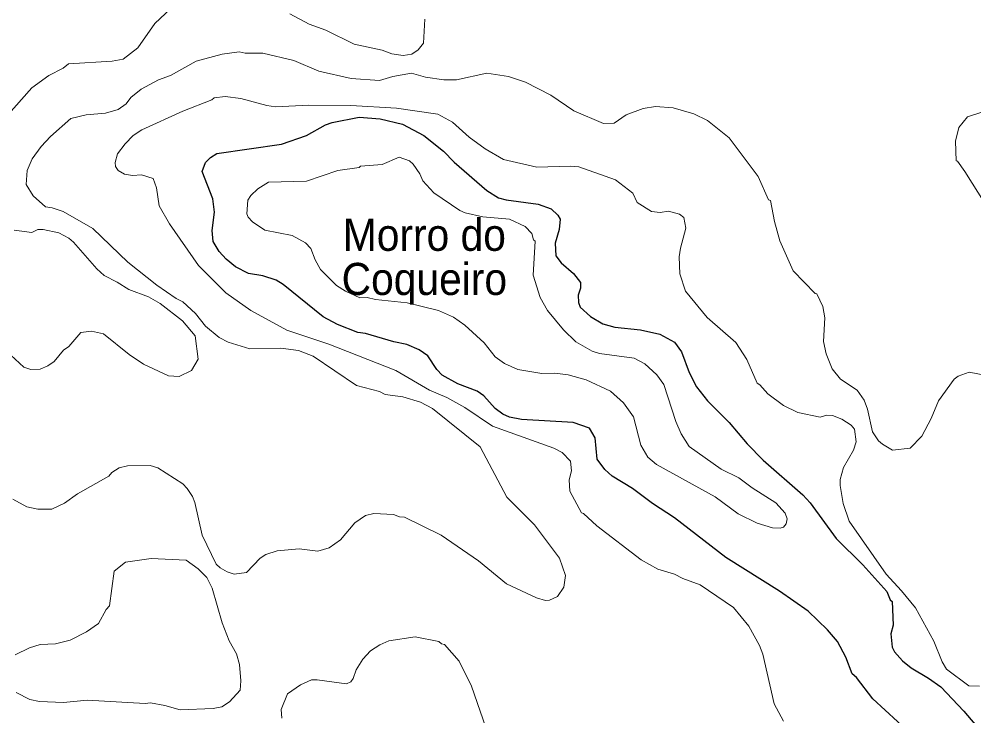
# Model space of a CAD drawing. Extents: x 447.8 to 473.9, y 7733.1 to 7760.8.
# Drawn here: x 456.578 to 458.959, y 7735.076 to 7736.813 of the extents above; entities that cross this region are included whole.
import ezdxf
from ezdxf.enums import TextEntityAlignment as Align

# ---------------------------------------------------------------- set-up
doc = ezdxf.new("R2010")
doc.units = 0
doc.header["$LTSCALE"] = 0.032
doc.layers.add('1', color=7, linetype='Continuous', lineweight=25)
doc.layers.add('2', color=7, linetype='Continuous', lineweight=13)
doc.layers.add('27', color=7, linetype='Continuous')

msp = doc.modelspace()

# ---------------------------------------------------------------- linework, layer by layer
at = {"layer": '1'}
for points in [[(458.7986, 7735.0336), (458.7063, 7735.1184), (458.6661, 7735.1714), (458.6556, 7735.1805), (458.6391, 7735.2227), (458.6189, 7735.2611), (458.5933, 7735.2907), (458.5457, 7735.3367), (458.4742, 7735.3871), (458.3405, 7735.4709), (458.2125, 7735.5693), (458.1571, 7735.6057), (458.1078, 7735.6428), (458.0567, 7735.6734), (458.0385, 7735.69), (458.0196, 7735.7159), (458.0148, 7735.7687), (458.0003, 7735.7929), (457.9595, 7735.8074), (457.8304, 7735.8148), (457.8005, 7735.8208), (457.7839, 7735.828), (457.7653, 7735.8422), (457.7369, 7735.8738), (457.7206, 7735.8852), (457.6722, 7735.9038), (457.6334, 7735.9256), (457.62, 7735.9396), (457.5972, 7735.9731), (457.576, 7735.988), (457.5446, 7736.0021), (457.5126, 7736.0086), (457.4416, 7736.0295), (457.4226, 7736.0315), (457.3718, 7736.0516), (457.3361, 7736.0703), (457.2367, 7736.1511), (457.2195, 7736.1622), (457.1855, 7736.173), (457.1502, 7736.1784), (457.1179, 7736.1955), (457.0943, 7736.2141), (457.0771, 7736.2337), (457.0618, 7736.258), (457.0594, 7736.2856), (457.065, 7736.3314), (457.0613, 7736.3647), (457.0346, 7736.4328), (457.0431, 7736.4556), (457.0551, 7736.4677), (457.0714, 7736.4776), (457.2324, 7736.5011), (457.295, 7736.523), (457.3423, 7736.5489), (457.3591, 7736.5547), (457.4257, 7736.5681), (457.4785, 7736.5641), (457.5338, 7736.5505), (457.5876, 7736.5222), (457.6359, 7736.4838), (457.6631, 7736.4565), (457.7441, 7736.3852), (457.7734, 7736.367), (457.7924, 7736.3622), (457.8726, 7736.3518), (457.9051, 7736.3395), (457.9215, 7736.324), (457.9274, 7736.3138), (457.925, 7736.2885), (457.9146, 7736.2544), (457.9162, 7736.2231), (457.9296, 7736.2053), (457.9603, 7736.1786), (457.9775, 7736.156), (457.9778, 7736.1419), (457.9724, 7736.1249), (457.9733, 7736.1066), (457.9772, 7736.0945), (458.0026, 7736.0716), (458.0338, 7736.0535), (458.0634, 7736.0448), (458.1278, 7736.0383), (458.1756, 7736.0272), (458.2125, 7736.0071), (458.2296, 7735.9838)], [(458.2296, 7735.9838), (458.249, 7735.9323), (458.2672, 7735.8959), (458.2941, 7735.8612), (458.3488, 7735.807), (458.3934, 7735.7543)], [(458.3934, 7735.7543), (458.4337, 7735.7132), (458.5321, 7735.6269), (458.5505, 7735.6068), (458.6157, 7735.5184), (458.6816, 7735.4525), (458.7416, 7735.3861), (458.7498, 7735.3653), (458.7545, 7735.3609), (458.757, 7735.3025), (458.7515, 7735.2808), (458.7547, 7735.2472), (458.7609, 7735.2354), (458.7806, 7735.2133), (458.802, 7735.1962), (458.8453, 7735.1705), (458.8762, 7735.1481), (458.934, 7735.0879), (459.0258, 7734.9793)]]:
    msp.add_lwpolyline(points, dxfattribs=at)
at = {"layer": '2'}
for points in [[(456.9701, 7736.8517), (456.9163, 7736.8019), (456.8745, 7736.741), (456.8377, 7736.7132), (456.8105, 7736.708), (456.7013, 7736.7016), (456.6878, 7736.6907), (456.6522, 7736.6724), (456.6102, 7736.6417), (456.5258, 7736.5476)], [(457.5897, 7736.8129), (457.5865, 7736.7524), (457.573, 7736.7364), (457.5576, 7736.725), (457.5356, 7736.7222), (457.5074, 7736.7262), (457.483, 7736.735), (457.4138, 7736.7504), (457.3432, 7736.785), (457.3016, 7736.8001), (457.2535, 7736.8258)], [(456.8449, 7736.6016), (456.8566, 7736.6171), (456.8824, 7736.6381), (456.9261, 7736.6614), (456.9556, 7736.6723), (457.0195, 7736.7077), (457.0841, 7736.7253), (457.1271, 7736.7309), (457.1415, 7736.7278), (457.1859, 7736.7276), (457.2629, 7736.7092), (457.3259, 7736.6833), (457.4058, 7736.6649), (457.4769, 7736.6596), (457.5098, 7736.6694), (457.5563, 7736.6779), (457.5913, 7736.6679), (457.6372, 7736.6611), (457.669, 7736.6613), (457.7447, 7736.6779), (457.7983, 7736.6699), (457.8405, 7736.6557), (457.904, 7736.623), (457.9615, 7736.5841), (458.0349, 7736.5522), (458.0614, 7736.5537), (458.0919, 7736.5742), (458.1345, 7736.5895), (458.1647, 7736.5946), (458.2087, 7736.5913), (458.2603, 7736.5769), (458.2946, 7736.5598), (458.3488, 7736.5164), (458.4208, 7736.4206), (458.4468, 7736.3626), (458.4515, 7736.3603), (458.4612, 7736.308), (458.4748, 7736.26), (458.5078, 7736.1853), (458.5631, 7736.1288), (458.5669, 7736.128), (458.5821, 7736.0968), (458.5871, 7736.0685), (458.584, 7736.0095), (458.5902, 7735.9785), (458.6054, 7735.9407), (458.6258, 7735.9149), (458.6679, 7735.8876), (458.6855, 7735.863), (458.6938, 7735.8408), (458.7055, 7735.7842), (458.7209, 7735.7613), (458.7304, 7735.7529), (458.7558, 7735.7386), (458.7998, 7735.7437), (458.829, 7735.7736), (458.8524, 7735.8172), (458.8704, 7735.8611), (458.9094, 7735.915), (458.9194, 7735.9227), (458.947, 7735.9325), (458.9857, 7735.9255)], [(456.6567, 7736.5199), (456.7075, 7736.5646), (456.7452, 7736.5745), (456.794, 7736.5786), (456.8253, 7736.5872), (456.8449, 7736.6016)], [(457.9499, 7735.6648), (457.9553, 7735.6869), (457.953, 7735.7109), (457.9319, 7735.7323), (457.9114, 7735.7433), (457.7583, 7735.7983), (457.6894, 7735.8448), (457.6449, 7735.8694), (457.6016, 7735.8878), (457.5173, 7735.9372), (457.3507, 7736.0029), (457.2457, 7736.0377), (457.1563, 7736.0863), (457.0937, 7736.1307), (457.0254, 7736.1989), (456.9529, 7736.3025), (456.9272, 7736.3474), (456.9207, 7736.3923), (456.9125, 7736.4158), (456.8837, 7736.4247), (456.861, 7736.4232), (456.8408, 7736.4263), (456.8255, 7736.4351), (456.8184, 7736.4457), (456.8181, 7736.4555), (456.8234, 7736.4768), (456.8423, 7736.5019), (456.8627, 7736.5223), (456.8845, 7736.5365), (456.9864, 7736.5836), (457.059, 7736.6114), (457.0642, 7736.6161), (457.0918, 7736.6195), (457.1311, 7736.6152), (457.196, 7736.5971), (457.2176, 7736.5938), (457.3003, 7736.5978), (457.4056, 7736.5971), (457.519, 7736.5906), (457.6225, 7736.5754), (457.6589, 7736.5561), (457.7, 7736.5183), (457.7398, 7736.4896), (457.786, 7736.4625), (457.8694, 7736.444), (457.9522, 7736.4464), (457.9739, 7736.4447), (458.0653, 7736.4121), (458.1082, 7736.3785), (458.1189, 7736.356), (458.1547, 7736.3335), (458.1763, 7736.331), (458.1971, 7736.334), (458.2243, 7736.3267), (458.2354, 7736.3182), (458.2407, 7736.2916), (458.2268, 7736.2419), (458.2241, 7736.2204), (458.2257, 7736.1778), (458.2394, 7736.1347), (458.2935, 7736.0691), (458.365, 7736.0063), (458.3923, 7735.9646), (458.418, 7735.9057), (458.425, 7735.9013), (458.4446, 7735.8784), (458.484, 7735.8498), (458.5196, 7735.8326), (458.5756, 7735.8204), (458.5923, 7735.8259), (458.6059, 7735.825), (458.6295, 7735.816), (458.6528, 7735.801), (458.6614, 7735.7909), (458.6655, 7735.7591), (458.6583, 7735.7382), (458.6337, 7735.6952), (458.6249, 7735.6656), (458.6249, 7735.6501), (458.6329, 7735.6052), (458.6477, 7735.5614), (458.74, 7735.4294), (458.7785, 7735.3877), (458.8128, 7735.345), (458.859, 7735.2621), (458.8799, 7735.2108), (458.8904, 7735.1924), (458.9464, 7735.1507), (458.9727, 7735.1502)], [(458.9865, 7736.3522), (458.9364, 7736.433), (458.9174, 7736.4587), (458.9141, 7736.4597), (458.9126, 7736.5084), (458.9214, 7736.5425), (458.9428, 7736.5693), (458.976, 7736.5802)], [(456.5624, 7735.616), (456.5974, 7735.5974), (456.625, 7735.5912), (456.6596, 7735.5912), (456.6914, 7735.6063), (456.7241, 7735.6299), (456.8019, 7735.6736), (456.8095, 7735.6825), (456.8279, 7735.6945), (456.8482, 7735.6993), (456.9046, 7735.7), (456.9237, 7735.6941), (456.9863, 7735.6544), (456.9975, 7735.6431), (457.0106, 7735.6228), (457.0167, 7735.6075), (457.0346, 7735.5266), (457.0694, 7735.4546), (457.0797, 7735.445), (457.0972, 7735.435), (457.1142, 7735.4292), (457.1455, 7735.4331), (457.1794, 7735.4689), (457.1932, 7735.478), (457.2213, 7735.4874), (457.2766, 7735.4925), (457.3234, 7735.4869), (457.3516, 7735.4947), (457.3793, 7735.5145), (457.4152, 7735.5574), (457.4418, 7735.5757), (457.4626, 7735.5806), (457.5119, 7735.5779), (457.527, 7735.5719), (457.5389, 7735.5713), (457.6308, 7735.5261), (457.7233, 7735.4626), (457.7937, 7735.4056), (457.8681, 7735.3702), (457.8909, 7735.3639), (457.9005, 7735.3643), (457.9209, 7735.374), (457.9362, 7735.3972), (457.9402, 7735.4259), (457.9258, 7735.4692), (457.8631, 7735.5521), (457.7946, 7735.6214), (457.7274, 7735.7467), (457.6087, 7735.8424), (457.5792, 7735.8582), (457.5346, 7735.8716), (457.491, 7735.8774), (457.4766, 7735.8845), (457.4196, 7735.8995), (457.3115, 7735.9727), (457.2746, 7735.9871), (457.2304, 7735.9926), (457.1531, 7735.9911), (457.0995, 7736.0071), (457.0774, 7736.0194), (457.043, 7736.0474), (457.0182, 7736.0786), (456.9866, 7736.1078), (456.9701, 7736.1163), (456.9219, 7736.1499), (456.8496, 7736.2068), (456.7622, 7736.2906), (456.6884, 7736.3332), (456.6606, 7736.3426), (456.6442, 7736.3449), (456.6136, 7736.372), (456.5961, 7736.4001), (456.5984, 7736.4356), (456.6109, 7736.4641), (456.6334, 7736.495), (456.6567, 7736.5199)], [(456.5663, 7736.2867), (456.6101, 7736.2805), (456.6248, 7736.2886), (456.6378, 7736.2885), (456.6775, 7736.2801), (456.7023, 7736.2666), (456.714, 7736.2569), (456.7718, 7736.1899), (456.7899, 7736.1733), (456.8226, 7736.1571), (456.852, 7736.1384), (456.9008, 7736.1204), (456.9297, 7736.1042), (456.9855, 7736.0608), (457.0168, 7736.0233), (457.0248, 7735.965), (457.0079, 7735.9366), (456.9772, 7735.9223), (456.9504, 7735.924), (456.8881, 7735.9527), (456.8526, 7735.9767), (456.789, 7736.0279), (456.7584, 7736.035), (456.7321, 7736.0317), (456.7023, 7735.9964), (456.6886, 7735.9874), (456.6655, 7735.9597), (456.6495, 7735.9484), (456.6304, 7735.9406), (456.6076, 7735.939), (456.5899, 7735.9453), (456.5577, 7735.9754)], [(458.1291, 7735.4654), (458.0183, 7735.55), (457.9856, 7735.5809), (457.9802, 7735.5818), (457.9512, 7735.6362), (457.9499, 7735.6648)], [(456.5706, 7735.134), (456.605, 7735.117), (456.6292, 7735.1117), (456.6888, 7735.1094), (456.7481, 7735.115), (456.8927, 7735.107), (456.9062, 7735.1085), (456.9415, 7735.1021), (456.9796, 7735.0909), (457.0624, 7735.0941), (457.0835, 7735.0987), (457.1028, 7735.1111), (457.1291, 7735.1404), (457.1307, 7735.1631), (457.1276, 7735.2045), (457.1203, 7735.2305), (457.1021, 7735.2635), (457.0846, 7735.3077), (457.0593, 7735.3948), (457.0464, 7735.4211), (457.0246, 7735.4428), (456.9944, 7735.4645), (456.9075, 7735.4684), (456.8438, 7735.4588), (456.815, 7735.437), (456.8036, 7735.3507), (456.7956, 7735.3415), (456.7758, 7735.3061), (456.7466, 7735.2852), (456.7059, 7735.2649), (456.6686, 7735.256), (456.6305, 7735.2544), (456.6045, 7735.2454), (456.5682, 7735.2281)], [(458.4839, 7735.0633), (458.461, 7735.1062), (458.4325, 7735.23), (458.4243, 7735.2515), (458.3977, 7735.2996), (458.3593, 7735.3458), (458.2761, 7735.4031), (458.2333, 7735.4181), (458.212, 7735.4294), (458.1708, 7735.4421), (458.1291, 7735.4654)], [(457.2332, 7735.0704), (457.2319, 7735.0917), (457.2477, 7735.1308), (457.2798, 7735.1534), (457.3073, 7735.166), (457.3215, 7735.1662), (457.3946, 7735.156), (457.405, 7735.1611), (457.4112, 7735.1695), (457.4186, 7735.1905), (457.4353, 7735.2178), (457.4545, 7735.2383), (457.4773, 7735.253), (457.4997, 7735.2633), (457.5659, 7735.2735), (457.6249, 7735.2617), (457.6312, 7735.256), (457.6391, 7735.2541), (457.6751, 7735.2124), (457.7063, 7735.1499), (457.771, 7734.963)]]:
    msp.add_lwpolyline(points, dxfattribs=at)
msp.add_lwpolyline([(457.9923, 7735.914), (458.0527, 7735.8858), (458.0848, 7735.8562), (458.1101, 7735.8217), (458.1284, 7735.7504), (458.1461, 7735.7212), (458.1677, 7735.7026), (458.3136, 7735.6217), (458.371, 7735.5797), (458.4187, 7735.5564), (458.4568, 7735.5445), (458.476, 7735.5438), (458.4842, 7735.5461), (458.4909, 7735.5544), (458.4933, 7735.567), (458.4883, 7735.5815), (458.465, 7735.6073), (458.4056, 7735.6446), (458.3729, 7735.669), (458.3288, 7735.6909), (458.2492, 7735.7478), (458.2287, 7735.7789), (458.2155, 7735.8097), (458.1857, 7735.9017), (458.1683, 7735.9259), (458.1385, 7735.9531), (458.1119, 7735.9677), (458.0249, 7735.9791), (458.0066, 7735.9852), (457.9665, 7736.0084), (457.9354, 7736.0383), (457.8954, 7736.0866), (457.8775, 7736.1192), (457.8602, 7736.1747), (457.8649, 7736.259), (457.861, 7736.2623), (457.8565, 7736.2784), (457.8402, 7736.2962), (457.8007, 7736.3141), (457.7346, 7736.3203), (457.6903, 7736.3297), (457.6767, 7736.3353), (457.6125, 7736.3798), (457.5846, 7736.41), (457.5777, 7736.4274), (457.5608, 7736.4514), (457.5514, 7736.4591), (457.5258, 7736.4688), (457.483, 7736.4503), (457.4292, 7736.4463), (457.426, 7736.443), (457.373, 7736.4352), (457.2947, 7736.4084), (457.2003, 7736.4063), (457.1731, 7736.3896), (457.1558, 7736.3731), (457.1485, 7736.3616), (457.1461, 7736.3273), (457.1491, 7736.3189), (457.1598, 7736.3077), (457.1909, 7736.2864), (457.2586, 7736.2733), (457.2922, 7736.2549), (457.3055, 7736.2408), (457.3161, 7736.2126), (457.3299, 7736.1885), (457.3693, 7736.1488), (457.3922, 7736.1344), (457.4279, 7736.1179), (457.4461, 7736.1186), (457.4666, 7736.1138), (457.5455, 7736.1057), (457.6235, 7736.0862), (457.6613, 7736.0696), (457.6899, 7736.0497), (457.7376, 7736.006), (457.7653, 7735.9713), (457.7885, 7735.9543), (457.8213, 7735.939), (457.8818, 7735.9294), (457.9137, 7735.9301), (457.947, 7735.9261)], close=True, dxfattribs=at)

# ---------------------------------------------------------------- texts
at = {"layer": '27', "width": 0.95}
for s, p in [('Morro do', (457.5886, 7736.2351)), ('Coqueiro', (457.5886, 7736.1251))]:
    msp.add_text(s, height=0.08, dxfattribs=at).set_placement(p, align=Align.CENTER)

doc.saveas('drawing.dxf')
